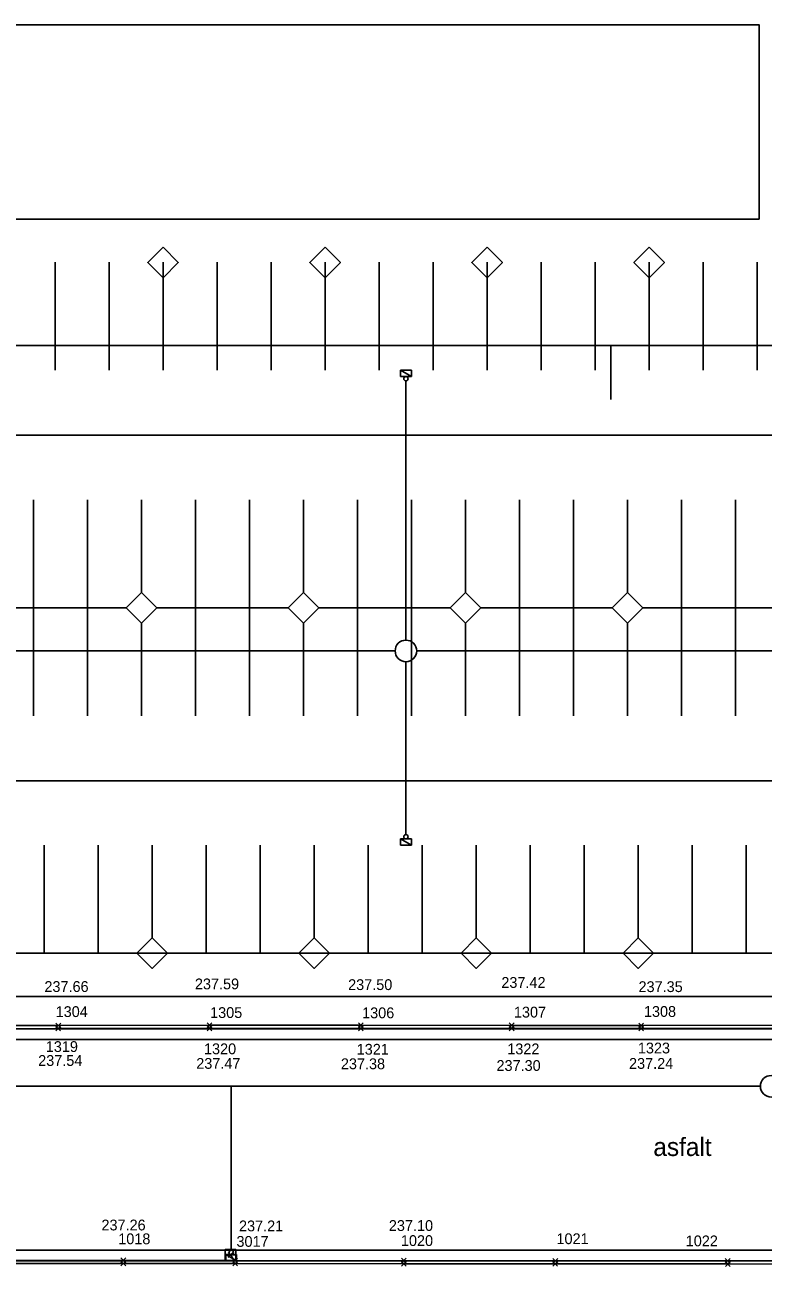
# Model space of a CAD drawing. Extents: x -264205 to -263615, y -1242401 to -1242031.
# Drawn here: x -263888.5 to -263854.3, y -1242312.5 to -1242255 of the extents above; entities that cross this region are included whole.
import ezdxf

# ---------------------------------------------------------------- set-up
doc = ezdxf.new("R2010")
doc.units = 0
for name, color, linetype in [('BODY_SYMBOL A CISLO_2-1', 7, 'Continuous'), ('BODY_VYSKA_2-1', 7, 'Continuous'), ('KOORDINACNA_SITUACIA_DSP', 7, 'Continuous'), ('POPIS', 7, 'Continuous'), ('PROJEKT_DRS_TDZ_VODOROVNE', 7, 'Continuous'), ('RAM_NA_TLAC_1-250_SITUACIA_2-1', 7, 'Continuous'), ('SO_20-1_OBRUBNIKY_DOLNA_HRANA', 7, 'Continuous'), ('SO_20-1_OBRUBNIKY_HORNA_HRANA', 7, 'Continuous'), ('SO_20-1_UV', 7, 'Continuous')]:
    doc.layers.add(name, color=color, linetype=linetype)

msp = doc.modelspace()

# ---------------------------------------------------------------- linework, layer by layer
at = {"layer": 'BODY_SYMBOL A CISLO_2-1'}
for p, q in [((-263887.028, -1242301.583), (-263886.807, -1242301.363)), ((-263886.807, -1242301.583), (-263887.028, -1242301.363)), ((-263887.027, -1242301.438), (-263886.806, -1242301.218)), ((-263886.806, -1242301.438), (-263887.027, -1242301.218)), ((-263880.033, -1242301.576), (-263879.812, -1242301.355)), ((-263879.812, -1242301.576), (-263880.033, -1242301.355)), ((-263880.031, -1242301.434), (-263879.81, -1242301.214)), ((-263879.81, -1242301.434), (-263880.031, -1242301.214)), ((-263873.022, -1242301.434), (-263872.801, -1242301.214)), ((-263872.801, -1242301.434), (-263873.022, -1242301.214)), ((-263873.02, -1242301.579), (-263872.799, -1242301.359)), ((-263872.799, -1242301.579), (-263873.02, -1242301.359)), ((-263866.04, -1242301.576), (-263865.818, -1242301.355)), ((-263865.818, -1242301.576), (-263866.04, -1242301.355)), ((-263866.039, -1242301.436), (-263865.818, -1242301.215)), ((-263865.818, -1242301.436), (-263866.039, -1242301.215)), ((-263860.042, -1242301.583), (-263859.821, -1242301.363)), ((-263859.821, -1242301.583), (-263860.042, -1242301.363)), ((-263860.041, -1242301.438), (-263859.82, -1242301.217)), ((-263859.82, -1242301.438), (-263860.041, -1242301.217)), ((-263879.057, -1242312.072), (-263878.837, -1242311.85)), ((-263878.837, -1242312.072), (-263879.057, -1242311.85)), ((-263884.018, -1242312.467), (-263883.796, -1242312.245)), ((-263883.796, -1242312.467), (-263884.018, -1242312.245)), ((-263884.016, -1242312.32), (-263883.795, -1242312.1)), ((-263883.795, -1242312.32), (-263884.016, -1242312.1)), ((-263878.842, -1242312.323), (-263878.621, -1242312.102)), ((-263878.621, -1242312.323), (-263878.842, -1242312.102)), ((-263878.842, -1242312.468), (-263878.621, -1242312.248)), ((-263878.621, -1242312.468), (-263878.842, -1242312.248)), ((-263871.035, -1242312.478), (-263870.813, -1242312.258)), ((-263870.813, -1242312.478), (-263871.035, -1242312.258)), ((-263871.034, -1242312.336), (-263870.812, -1242312.116)), ((-263870.812, -1242312.336), (-263871.034, -1242312.116)), ((-263864.024, -1242312.478), (-263863.802, -1242312.258)), ((-263863.802, -1242312.478), (-263864.024, -1242312.258)), ((-263864.018, -1242312.343), (-263863.796, -1242312.122)), ((-263863.796, -1242312.343), (-263864.018, -1242312.122)), ((-263856.041, -1242312.343), (-263855.819, -1242312.122)), ((-263855.819, -1242312.343), (-263856.041, -1242312.122)), ((-263856.036, -1242312.488), (-263855.815, -1242312.268)), ((-263855.815, -1242312.488), (-263856.036, -1242312.268))]:
    msp.add_line(p, q, dxfattribs=at)
at = {"layer": 'KOORDINACNA_SITUACIA_DSP'}
for p, q in [((-263871.074, -1242270.983), (-263870.574, -1242270.983)), ((-263871.074, -1242271.273), (-263871.074, -1242270.983)), ((-263871.074, -1242270.983), (-263870.574, -1242271.273)), ((-263871.074, -1242270.983), (-263870.574, -1242271.273)), ((-263870.574, -1242270.983), (-263871.074, -1242270.983)), ((-263870.574, -1242270.983), (-263870.574, -1242271.273)), ((-263870.574, -1242271.273), (-263870.574, -1242270.983)), ((-263870.574, -1242271.273), (-263871.074, -1242271.273)), ((-263870.824, -1242271.473), (-263870.824, -1242283.482)), ((-263871.324, -1242283.982), (-263903.413, -1242283.982)), ((-263817.941, -1242283.982), (-263870.324, -1242283.982)), ((-263817.941, -1242283.982), (-263870.324, -1242283.982)), ((-263870.824, -1242292.492), (-263870.824, -1242284.482)), ((-263871.074, -1242292.693), (-263870.574, -1242292.693)), ((-263871.074, -1242292.983), (-263871.074, -1242292.693)), ((-263871.074, -1242292.693), (-263870.574, -1242292.983)), ((-263871.074, -1242292.693), (-263870.574, -1242292.983)), ((-263870.574, -1242292.693), (-263871.074, -1242292.693)), ((-263870.574, -1242292.983), (-263871.074, -1242292.983)), ((-263870.574, -1242292.693), (-263870.574, -1242292.983)), ((-263870.574, -1242292.983), (-263870.574, -1242292.693)), ((-263815.601, -1242297.982), (-263917.08, -1242297.982)), ((-263816.308, -1242299.982), (-263918.049, -1242299.982)), ((-263914.08, -1242301.482), (-263815.822, -1242301.482)), ((-263854.415, -1242304.147), (-263903.413, -1242304.147)), ((-263878.913, -1242311.742), (-263878.913, -1242304.147)), ((-263879.163, -1242311.942), (-263878.663, -1242311.942)), ((-263879.163, -1242312.232), (-263879.163, -1242311.942)), ((-263879.163, -1242311.942), (-263878.663, -1242312.232)), ((-263879.163, -1242311.942), (-263878.663, -1242312.232)), ((-263878.663, -1242311.942), (-263879.163, -1242311.942)), ((-263878.663, -1242311.942), (-263878.663, -1242312.232)), ((-263878.663, -1242312.232), (-263878.663, -1242311.942)), ((-263980.94, -1242312.232), (-263857.327, -1242312.232)), ((-263842.601, -1242312.24), (-263924.192, -1242312.232)), ((-263878.663, -1242312.232), (-263879.163, -1242312.232))]:
    msp.add_line(p, q, dxfattribs=at)
msp.add_lwpolyline([(-263854.468, -1242263.985), (-263917.08, -1242263.982), (-263901.868, -1242254.982), (-263854.468, -1242254.985), (-263854.468, -1242263.985)], dxfattribs=at)
for points in [[(-263882.068, -1242265.279), (-263881.361, -1242265.986), (-263882.068, -1242266.693), (-263882.775, -1242265.986)], [(-263874.568, -1242265.279), (-263873.861, -1242265.986), (-263874.568, -1242266.693), (-263875.275, -1242265.986)], [(-263867.068, -1242265.279), (-263866.361, -1242265.986), (-263867.068, -1242266.693), (-263867.775, -1242265.986)], [(-263859.568, -1242265.279), (-263858.861, -1242265.986), (-263859.568, -1242266.693), (-263860.275, -1242265.986)], [(-263883.068, -1242281.275), (-263882.361, -1242281.982), (-263883.068, -1242282.689), (-263883.775, -1242281.982)], [(-263875.568, -1242281.275), (-263874.861, -1242281.982), (-263875.568, -1242282.689), (-263876.275, -1242281.982)], [(-263868.068, -1242281.275), (-263867.361, -1242281.982), (-263868.068, -1242282.689), (-263868.775, -1242281.982)], [(-263860.568, -1242281.275), (-263859.861, -1242281.982), (-263860.568, -1242282.689), (-263861.275, -1242281.982)], [(-263882.568, -1242297.275), (-263881.861, -1242297.982), (-263882.568, -1242298.689), (-263883.275, -1242297.982)], [(-263875.068, -1242297.275), (-263874.361, -1242297.982), (-263875.068, -1242298.689), (-263875.775, -1242297.982)], [(-263867.568, -1242297.275), (-263866.861, -1242297.982), (-263867.568, -1242298.689), (-263868.275, -1242297.982)], [(-263860.068, -1242297.275), (-263859.361, -1242297.982), (-263860.068, -1242298.689), (-263860.775, -1242297.982)]]:
    msp.add_lwpolyline(points, close=True, dxfattribs=at)
for centre, radius in [((-263870.824, -1242271.373), 0.1), ((-263870.824, -1242283.982), 0.5), ((-263870.824, -1242292.592), 0.1), ((-263853.915, -1242304.147), 0.5), ((-263878.913, -1242311.842), 0.1)]:
    msp.add_circle(centre, radius, dxfattribs=at)
at = {"layer": 'PROJEKT_DRS_TDZ_VODOROVNE'}
for p, q in [((-263887.068, -1242270.982), (-263887.068, -1242265.982)), ((-263884.568, -1242270.982), (-263884.568, -1242265.982)), ((-263882.068, -1242270.982), (-263882.068, -1242265.982)), ((-263879.568, -1242270.982), (-263879.568, -1242265.982)), ((-263877.068, -1242270.982), (-263877.068, -1242265.982)), ((-263874.568, -1242270.982), (-263874.568, -1242265.982)), ((-263872.068, -1242270.982), (-263872.068, -1242265.982)), ((-263869.568, -1242270.982), (-263869.568, -1242265.982)), ((-263867.068, -1242270.982), (-263867.068, -1242265.982)), ((-263864.568, -1242270.982), (-263864.568, -1242265.982)), ((-263862.068, -1242270.982), (-263862.068, -1242265.982)), ((-263859.568, -1242270.982), (-263859.568, -1242265.982)), ((-263857.068, -1242270.982), (-263857.068, -1242265.982)), ((-263854.568, -1242270.982), (-263854.568, -1242265.982)), ((-263817.068, -1242273.982), (-263917.477, -1242273.982)), ((-263888.068, -1242281.982), (-263888.068, -1242276.982)), ((-263885.568, -1242281.982), (-263885.568, -1242276.982)), ((-263883.068, -1242281.275), (-263883.068, -1242276.982)), ((-263880.568, -1242281.982), (-263880.568, -1242276.982)), ((-263878.068, -1242281.982), (-263878.068, -1242276.982)), ((-263875.568, -1242281.275), (-263875.568, -1242276.982)), ((-263873.068, -1242281.982), (-263873.068, -1242276.982)), ((-263870.568, -1242281.982), (-263870.568, -1242276.982)), ((-263868.068, -1242281.275), (-263868.068, -1242276.982)), ((-263865.568, -1242281.982), (-263865.568, -1242276.982)), ((-263863.068, -1242281.982), (-263863.068, -1242276.982)), ((-263860.568, -1242281.275), (-263860.568, -1242276.982)), ((-263858.068, -1242281.982), (-263858.068, -1242276.982)), ((-263855.568, -1242281.982), (-263855.568, -1242276.982)), ((-263883.775, -1242281.982), (-263889.861, -1242281.982)), ((-263888.068, -1242286.982), (-263888.068, -1242281.982)), ((-263885.568, -1242286.982), (-263885.568, -1242281.982)), ((-263876.275, -1242281.982), (-263882.361, -1242281.982)), ((-263880.568, -1242286.982), (-263880.568, -1242281.982)), ((-263878.068, -1242286.982), (-263878.068, -1242281.982)), ((-263868.775, -1242281.982), (-263874.861, -1242281.982)), ((-263873.068, -1242286.982), (-263873.068, -1242281.982)), ((-263870.568, -1242286.982), (-263870.568, -1242281.982)), ((-263861.275, -1242281.982), (-263867.361, -1242281.982)), ((-263865.568, -1242286.982), (-263865.568, -1242281.982)), ((-263863.068, -1242286.982), (-263863.068, -1242281.982)), ((-263853.775, -1242281.982), (-263859.861, -1242281.982)), ((-263858.068, -1242286.982), (-263858.068, -1242281.982)), ((-263855.568, -1242286.982), (-263855.568, -1242281.982)), ((-263883.068, -1242286.982), (-263883.068, -1242282.689)), ((-263875.568, -1242286.982), (-263875.568, -1242282.689)), ((-263868.068, -1242286.982), (-263868.068, -1242282.689)), ((-263860.568, -1242286.982), (-263860.568, -1242282.689)), ((-263819.531, -1242289.994), (-263917.477, -1242289.994)), ((-263887.568, -1242297.982), (-263887.568, -1242292.982)), ((-263885.068, -1242297.982), (-263885.068, -1242292.982)), ((-263882.568, -1242297.275), (-263882.568, -1242292.982)), ((-263880.068, -1242297.982), (-263880.068, -1242292.982)), ((-263877.568, -1242297.982), (-263877.568, -1242292.982)), ((-263875.068, -1242297.275), (-263875.068, -1242292.982)), ((-263872.568, -1242297.982), (-263872.568, -1242292.982)), ((-263870.068, -1242297.982), (-263870.068, -1242292.982)), ((-263867.568, -1242297.275), (-263867.568, -1242292.982)), ((-263865.068, -1242297.982), (-263865.068, -1242292.982)), ((-263862.568, -1242297.982), (-263862.568, -1242292.982)), ((-263860.068, -1242297.275), (-263860.068, -1242292.982)), ((-263857.568, -1242297.982), (-263857.568, -1242292.982)), ((-263855.068, -1242297.982), (-263855.068, -1242292.982)), ((-263913.857, -1242301.982), (-263816.374, -1242301.982)), ((-263842.661, -1242311.732), (-263980.94, -1242311.732))]:
    msp.add_line(p, q, dxfattribs=at)
at = {"layer": 'RAM_NA_TLAC_1-250_SITUACIA_2-1'}
msp.add_line((-263861.333, -1242269.835), (-263861.333, -1242272.335), dxfattribs=at)
msp.add_lwpolyline([(-264151.333, -1242269.835), (-263718.833, -1242269.835), (-263718.833, -1242344.085), (-264151.333, -1242344.085)], close=True, dxfattribs=at)
at = {"layer": 'SO_20-1_OBRUBNIKY_DOLNA_HRANA'}
for points in [[(-263913.884, -1242301.489), (-263907.893, -1242301.489), (-263900.89, -1242301.488), (-263893.898, -1242301.483), (-263886.917, -1242301.473), (-263879.922, -1242301.465), (-263872.91, -1242301.469), (-263865.929, -1242301.465), (-263859.932, -1242301.473), (-263850.941, -1242301.471), (-263843.947, -1242301.471), (-263836.942, -1242301.481), (-263829.943, -1242301.484), (-263823.945, -1242301.487), (-263818.452, -1242301.495), (-263816.42, -1242301.504)], [(-263927.909, -1242312.235), (-263920.91, -1242312.234), (-263913.915, -1242312.225), (-263906.912, -1242312.227), (-263898.896, -1242312.208), (-263891.9, -1242312.209), (-263883.905, -1242312.21), (-263878.731, -1242312.212), (-263870.923, -1242312.226), (-263863.907, -1242312.232), (-263855.93, -1242312.232)], [(-263855.93, -1242312.232), (-263849.929, -1242312.239), (-263843.916, -1242312.251), (-263841.932, -1242312.261)]]:
    msp.add_lwpolyline(points, dxfattribs=at)
at = {"layer": 'SO_20-1_OBRUBNIKY_HORNA_HRANA'}
for points in [[(-263913.884, -1242301.344), (-263907.893, -1242301.343), (-263900.896, -1242301.344), (-263893.895, -1242301.338), (-263886.916, -1242301.328), (-263879.921, -1242301.324), (-263872.911, -1242301.324), (-263865.928, -1242301.325), (-263859.931, -1242301.327), (-263850.935, -1242301.324), (-263843.941, -1242301.331), (-263836.939, -1242301.332), (-263829.941, -1242301.342), (-263823.94, -1242301.343), (-263818.456, -1242301.352), (-263816.413, -1242301.358)], [(-263927.907, -1242312.381), (-263920.909, -1242312.378), (-263913.91, -1242312.365), (-263906.907, -1242312.358), (-263898.91, -1242312.357), (-263891.902, -1242312.354), (-263883.907, -1242312.356), (-263878.731, -1242312.358), (-263870.924, -1242312.368), (-263863.913, -1242312.368), (-263855.926, -1242312.378)], [(-263855.926, -1242312.378), (-263849.928, -1242312.38), (-263843.916, -1242312.392), (-263841.931, -1242312.403)]]:
    msp.add_lwpolyline(points, dxfattribs=at)
at = {"layer": 'SO_20-1_UV'}
msp.add_line((-263878.947, -1242311.961), (-263878.947, -1242311.961), dxfattribs=at)
msp.add_lwpolyline([(-263879.197, -1242311.961), (-263879.197, -1242311.711), (-263878.697, -1242311.711), (-263878.697, -1242312.211), (-263879.197, -1242312.211), (-263879.197, -1242311.961), (-263878.697, -1242311.961)], dxfattribs=at)

# ---------------------------------------------------------------- texts
at = {"layer": 'BODY_SYMBOL A CISLO_2-1'}
for s, p in [('1304', (-263887.039, -1242300.94)), ('1307', (-263865.826, -1242300.963)), ('1308', (-263859.808, -1242300.934)), ('1305', (-263879.889, -1242300.984)), ('1306', (-263872.853, -1242300.996)), ('1319', (-263887.495, -1242302.559)), ('1320', (-263880.172, -1242302.663)), ('1321', (-263873.103, -1242302.683)), ('1322', (-263866.133, -1242302.666)), ('1323', (-263860.088, -1242302.626)), ('1018', (-263884.141, -1242311.463)), ('3017', (-263878.669, -1242311.584)), ('1020', (-263871.057, -1242311.546)), ('1021', (-263863.856, -1242311.459)), ('1022', (-263857.873, -1242311.56))]:
    msp.add_text(s, height=0.5, dxfattribs=at).set_placement(p)
at = {"layer": 'BODY_VYSKA_2-1'}
for s, p in [('237.66', (-263887.559, -1242299.778)), ('237.59', (-263880.592, -1242299.656)), ('237.50', (-263873.501, -1242299.69)), ('237.42', (-263866.407, -1242299.589)), ('237.35', (-263860.058, -1242299.784)), ('237.54', (-263887.848, -1242303.204)), ('237.47', (-263880.531, -1242303.339)), ('237.38', (-263873.836, -1242303.356)), ('237.30', (-263866.633, -1242303.436)), ('237.24', (-263860.497, -1242303.34)), ('237.26', (-263884.919, -1242310.824)), ('237.21', (-263878.551, -1242310.865)), ('237.10', (-263871.615, -1242310.848))]:
    msp.add_text(s, height=0.5, dxfattribs=at).set_placement(p)
at = {"layer": 'POPIS'}
msp.add_text('asfalt', height=0.8438, dxfattribs=at).set_placement((-263859.372, -1242307.377))

doc.saveas('drawing.dxf')
